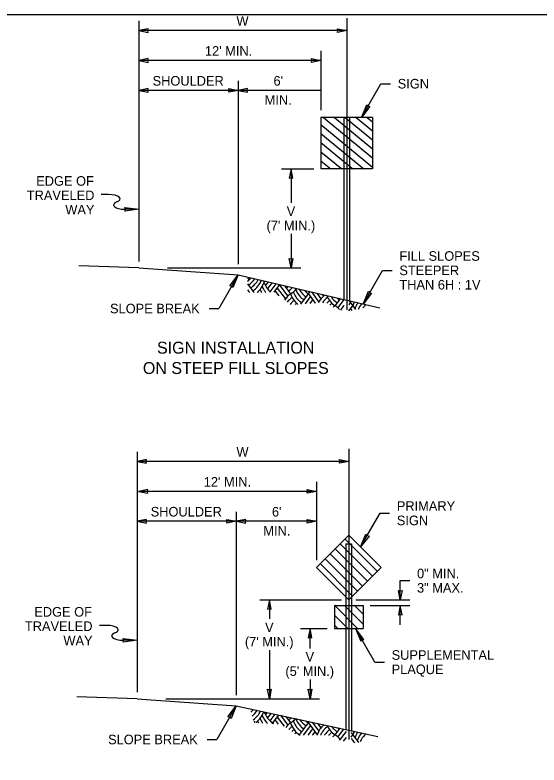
# Model space of a CAD drawing. Extents: x 99862 to 104211, y 98939 to 102076.
# Drawn here: x 100694 to 101570, y 100822 to 102076 of the extents above; entities that cross this region are included whole.
import ezdxf

# ---------------------------------------------------------------- set-up
doc = ezdxf.new("R2010")
doc.units = 0
for name, color, linetype in [('Level 1', 7, 'Continuous'), ('Level 14', 7, 'Continuous'), ('Level 15', 7, 'Continuous'), ('Level 2', 7, 'Continuous'), ('Level 20', 7, 'Continuous'), ('Level 6', 7, 'Continuous')]:
    doc.layers.add(name, color=color, linetype=linetype)

msp = doc.modelspace()

# ---------------------------------------------------------------- linework, layer by layer
at = {"layer": 'Level 1'}
msp.add_lwpolyline([(99862, 99999.5), (103151, 99999.5), (103151, 102075.5), (99862, 102075.5)], close=True, dxfattribs=at)
msp.add_lwpolyline([(99862, 99999.5), (103151, 99999.5), (103151, 102075.5), (99862, 102075.5)], close=True, dxfattribs=at)
at = {"layer": 'Level 14'}
for p, q in [((100850.7, 101775.4), (100838.4, 101775.4)), ((100897.2, 101750.8), (100878, 101750.8)), ((100847.5, 101055.4), (100835.2, 101055.4)), ((100894, 101030.8), (100874.8, 101030.8))]:
    msp.add_line(p, q, dxfattribs=at)
for points in [[(100901.2, 101750.8), (100877.9, 101747.8), (100879, 101750.8), (100877.9, 101753.9)], [(100898.1, 101030.8), (100874.7, 101027.7), (100875.8, 101030.8), (100874.7, 101033.8)]]:
    msp.add_lwpolyline(points, close=True, dxfattribs=at)
for centre, start_param, end_param in [((100850.8, 101768.2), 5.497747, 7.861127), ((100878, 101758), 2.356226, 4.712389), ((100847.7, 101048.2), 5.497747, 7.861127), ((100874.8, 101038), 2.356226, 4.712389)]:
    msp.add_ellipse(centre, major_axis=(19.2, 0), ratio=0.375, start_param=start_param, end_param=end_param, dxfattribs=at)
at = {"layer": 'Level 15'}
for p, q in [((100901.2, 102065.5), (100901.2, 101663.8)), ((101248.9, 102049.5), (100901.2, 102049.5)), ((101205.5, 102015.5), (101205.5, 101916.4)), ((101205.5, 101999.5), (100901.2, 101999.5)), ((101067.1, 101965.5), (101067.1, 101659.1)), ((101273.3, 101904.4), (101305.8, 101960.7)), ((101305.8, 101960.7), (101321.8, 101960.7)), ((101067.1, 101949.5), (100901.2, 101949.5)), ((101205.5, 101949.5), (101067.1, 101949.5)), ((101139.6, 101818.3), (101193.5, 101818.3)), ((101155.6, 101818.3), (101155.6, 101761.7)), ((101155.6, 101709.7), (101155.6, 101653.1)), ((100949.2, 101653.1), (101171.6, 101653.1)), ((101067.1, 101641.3), (101034.6, 101585)), ((101276.1, 101592.5), (101308.6, 101648.8)), ((101308.6, 101648.8), (101324.6, 101648.8)), ((101018.6, 101585), (101034.6, 101585)), ((100898.1, 101345.5), (100898.1, 100943.8)), ((101252, 101329.5), (100898.1, 101329.5)), ((101197.9, 101295.5), (101197.9, 101164.4)), ((101197.9, 101279.5), (100900.5, 101279.5)), ((101064, 101245.5), (101064, 100939.1)), ((101271.8, 101186.7), (101304.3, 101243)), ((101304.3, 101243), (101320.3, 101243)), ((101064, 101229.5), (100898.1, 101229.5)), ((101197.9, 101229.5), (101064, 101229.5)), ((101338.1, 101130.3), (101354.1, 101130.3)), ((101338.1, 101098.3), (101338.1, 101130.3)), ((101103.4, 101098.3), (101240, 101098.3)), ((101119.4, 101098.3), (101119.4, 101066.3)), ((101264, 101098.3), (101354.1, 101098.3)), ((101287.9, 101088.7), (101354.1, 101088.7)), ((101338.1, 101056.7), (101338.1, 101088.7)), ((101171.2, 101050.4), (101216.1, 101050.4)), ((101187.2, 101017.1), (101187.2, 101050.4)), ((101295.6, 100994.1), (101263.1, 101050.4)), ((101119.4, 101014.3), (101119.4, 100933.1)), ((101295.6, 100994.1), (101311.6, 100994.1)), ((101187.2, 100965.1), (101187.2, 100933.1)), ((100946.1, 100933.1), (101203.2, 100933.1)), ((101064, 100921.2), (101031.5, 100864.9)), ((101015.5, 100864.9), (101031.5, 100864.9))]:
    msp.add_line(p, q, dxfattribs=at)
for points in [[(100901.2, 102049.5), (100917, 102046.4), (100916.2, 102049.5), (100917, 102052.6)], [(101248.9, 102049.5), (101233.1, 102046.4), (101233.9, 102049.5), (101233.1, 102052.6)], [(100901.2, 101999.5), (100917, 101996.4), (100916.2, 101999.5), (100917, 102002.6)], [(101205.5, 101999.5), (101189.7, 101996.4), (101190.5, 101999.5), (101189.7, 102002.6)], [(100901.2, 101949.5), (100917, 101946.4), (100916.2, 101949.5), (100917, 101952.6)], [(101067.1, 101949.5), (101051.4, 101946.4), (101052.2, 101949.5), (101051.4, 101952.6)], [(101067.1, 101949.5), (101082.9, 101946.4), (101082.1, 101949.5), (101082.9, 101952.6)], [(101273.3, 101904.4), (101282.2, 101925.6), (101284.2, 101923.2), (101287.3, 101922.7)], [(101155.6, 101818.3), (101152.5, 101802.6), (101155.6, 101803.3), (101158.7, 101802.6)], [(101155.6, 101653.1), (101152.5, 101668.8), (101155.6, 101668.1), (101158.7, 101668.8)], [(101067.1, 101641.3), (101058.3, 101620), (101056.3, 101622.4), (101053.1, 101623)], [(101276.1, 101592.5), (101284.9, 101613.8), (101287, 101611.3), (101290.1, 101610.8)], [(100898.1, 101329.5), (100913.8, 101326.4), (100913.1, 101329.5), (100913.8, 101332.5)], [(101252, 101329.5), (101236.3, 101326.4), (101237, 101329.5), (101236.3, 101332.5)], [(100900.5, 101279.5), (100916.2, 101276.4), (100915.5, 101279.5), (100916.2, 101282.5)], [(101197.9, 101279.5), (101182.2, 101276.4), (101182.9, 101279.5), (101182.2, 101282.5)], [(100898.1, 101229.5), (100913.8, 101226.4), (100913.1, 101229.5), (100913.8, 101232.5)], [(101064, 101229.5), (101048.3, 101226.4), (101049, 101229.5), (101048.3, 101232.5)], [(101064, 101229.5), (101079.7, 101226.4), (101079, 101229.5), (101079.7, 101232.5)], [(101197.9, 101229.5), (101182.2, 101226.4), (101182.9, 101229.5), (101182.2, 101232.5)], [(101271.8, 101186.7), (101280.6, 101207.9), (101282.7, 101205.5), (101285.8, 101204.9)], [(101338.1, 101098.3), (101335, 101114), (101338.1, 101113.2), (101341.2, 101114)], [(101119.4, 101098.3), (101116.4, 101082.5), (101119.4, 101083.3), (101122.5, 101082.5)], [(101338.1, 101088.7), (101335, 101073), (101338.1, 101073.7), (101341.2, 101073)], [(101187.2, 101050.4), (101184.1, 101034.7), (101187.2, 101035.4), (101190.3, 101034.7)], [(101263.1, 101050.4), (101271.9, 101029.2), (101273.9, 101031.6), (101277.1, 101032.2)], [(101119.4, 100933.1), (101116.4, 100948.8), (101119.4, 100948.1), (101122.5, 100948.8)], [(101187.2, 100933.1), (101184.1, 100948.8), (101187.2, 100948.1), (101190.3, 100948.8)], [(101064, 100921.2), (101055.2, 100900), (101053.1, 100902.4), (101050, 100902.9)]]:
    msp.add_lwpolyline(points, close=True, dxfattribs=at)
at = {"layer": 'Level 2'}
for p, q in [((101248.5, 102070.3), (101248.5, 101582.9)), ((101205.5, 101904.4), (101205.5, 101818.3)), ((101291.5, 101904.4), (101205.5, 101904.4)), ((101209.5, 101904.4), (101291.5, 101836.6)), ((101227.9, 101904.4), (101291.5, 101851.7)), ((101243.7, 101904.4), (101243.7, 101818.3)), ((101246.2, 101904.4), (101291.5, 101866.9)), ((101253.3, 101904.4), (101253.3, 101818.3)), ((101264.6, 101904.4), (101291.5, 101882.1)), ((101282.9, 101904.4), (101291.5, 101897.2)), ((101291.5, 101904.4), (101291.5, 101818.3)), ((101205.5, 101892.6), (101291.5, 101821.4)), ((101205.5, 101877.4), (101276.9, 101818.3)), ((101205.5, 101862.2), (101258.6, 101818.3)), ((101205.5, 101847.1), (101240.3, 101818.3)), ((101205.5, 101831.9), (101221.9, 101818.3)), ((101291.5, 101818.3), (101205.5, 101818.3)), ((101243.7, 101818.3), (101243.7, 101600.1)), ((101253.3, 101818.3), (101253.3, 101597.8)), ((100901.2, 101653.1), (100800.8, 101656.2)), ((100901.2, 101653.1), (101067.1, 101641.3)), ((101067.1, 101641.3), (101303.9, 101586)), ((101252, 101350.3), (101252, 100864.6)), ((101252, 101206.5), (101197.9, 101152.4)), ((101245.6, 101200.1), (101299.7, 101146)), ((101306.1, 101152.4), (101252, 101206.5)), ((101237.4, 101191.8), (101291.5, 101137.7)), ((101247.2, 101191.7), (101256.8, 101191.7)), ((101247.2, 101191.7), (101247.2, 101105)), ((101256.8, 101191.7), (101256.8, 101103.9)), ((101220.8, 101175.3), (101274.9, 101121.2)), ((101229.1, 101183.5), (101283.2, 101129.4)), ((101212.6, 101167), (101266.7, 101112.9)), ((101197.9, 101152.4), (101252, 101098.3)), ((101204.3, 101158.7), (101258.4, 101104.6)), ((101252, 101098.3), (101306.1, 101152.4)), ((101247.2, 101103.6), (101247.2, 101088.7)), ((101256.8, 101103.3), (101256.8, 101089.3)), ((101228.1, 101089.1), (101266.8, 101050.4)), ((101228.1, 101088.7), (101275.9, 101088.7)), ((101228.1, 101088.7), (101228.1, 101050.4)), ((101245, 101088.7), (101275.9, 101057.8)), ((101247.2, 101088.7), (101247.2, 101050.4)), ((101256.8, 101089.3), (101256.8, 101050.4)), ((101261, 101089.3), (101275.9, 101074.3)), ((101275.9, 101088.7), (101275.9, 101050.4)), ((101228.1, 101072.6), (101250.2, 101050.4)), ((101228.1, 101056), (101233.7, 101050.4)), ((101228.1, 101050.4), (101275.9, 101050.4)), ((101247.2, 101050.4), (101247.2, 100881.6)), ((101256.8, 101050.4), (101256.8, 100879.5)), ((100898.1, 100933.1), (100797.6, 100936.2)), ((100898.1, 100933.1), (101064, 100921.2)), ((101064, 100921.2), (101300.3, 100870.1))]:
    msp.add_line(p, q, dxfattribs=at)
msp.add_lwpolyline([(101067.1, 101641.3), (101065.3, 101639.4), (101065.8, 101639.2), (101066.1, 101638.9)], close=True, dxfattribs=at)
at = {"layer": 'Level 6'}
for p, q in [((101082.6, 101636.4), (101085.3, 101632.9)), ((101082.7, 101626.4), (101093.6, 101611.8)), ((101110.3, 101629.2), (101111.6, 101630.9)), ((101113, 101622.9), (101117.9, 101629.4)), ((101116.4, 101617.6), (101124.2, 101627.9)), ((101120.5, 101613.1), (101130.5, 101626.5)), ((101127.2, 101612.1), (101136.8, 101625)), ((101082.8, 101616.4), (101086.3, 101611.7)), ((101128.9, 101614.3), (101135, 101606.1)), ((101132.6, 101619.3), (101146.1, 101601.2)), ((101136.3, 101624.2), (101150.2, 101605.7)), ((101144.5, 101623.2), (101154.8, 101609.4)), ((101179.9, 101613.1), (101181.1, 101614.7)), ((101184.5, 101609.4), (101187.4, 101613.2)), ((101189.5, 101612.7), (101202.1, 101595.9)), ((101171.7, 101592.3), (101184.5, 101609.4)), ((101179.5, 101592.8), (101188.3, 101604.4)), ((101184.5, 101609.4), (101196.1, 101593.9)), ((101187.4, 101593.4), (101192, 101599.5)), ((101198.5, 101610.6), (101205.5, 101601.2)), ((101207.5, 101608.5), (101209.6, 101605.7)), ((101229.1, 101589.6), (101237.9, 101601.4)), ((101236.5, 101589.6), (101244.3, 101599.9)), ((101195.2, 101593.9), (101195.7, 101594.5)), ((101233.7, 101585.9), (101236.5, 101589.6)), ((101238.6, 101582.5), (101243.9, 101589.6)), ((101243.9, 101589.6), (101244.5, 101590.3)), ((101252.3, 101581), (101258.8, 101589.6)), ((101252.5, 101598), (101258.8, 101589.6)), ((101252.5, 101591.1), (101255.1, 101594.5)), ((101258.8, 101589.6), (101263.5, 101583.4)), ((101255.1, 101584.6), (101257.1, 101582)), ((101113, 100905.9), (101116, 100910)), ((101116.4, 100900.6), (101122.4, 100908.6)), ((101120.5, 100896.2), (101128.8, 100907.2)), ((101125.1, 100892.5), (101135.2, 100905.8)), ((101132.6, 100902.4), (101144.1, 100887)), ((101137.8, 100905.3), (101150.2, 100888.8)), ((101146.7, 100903.3), (101154.8, 100892.5)), ((101093.1, 100895.6), (101094.9, 100893.2)), ((101124.2, 100891.2), (101125.1, 100892.5)), ((101125.1, 100892.5), (101126.2, 100891.1)), ((101128.9, 100897.4), (101134, 100890.6)), ((101169.7, 100872.7), (101184.5, 100892.5)), ((101177.1, 100872.7), (101188.3, 100887.5)), ((101184.5, 100892.5), (101186.3, 100894.8)), ((101184.5, 100892.5), (101199.4, 100872.7)), ((101191, 100893.8), (101202.1, 100879)), ((101199.9, 100891.8), (101205.5, 100884.3)), ((101208.7, 100889.9), (101209.6, 100888.8)), ((101176.6, 100872), (101177.1, 100872.7)), ((101184, 100872), (101184.5, 100872.7)), ((101184.5, 100872.7), (101192, 100882.6)), ((101191.5, 100872), (101192, 100872.7)), ((101192, 100872.7), (101195.7, 100877.6)), ((101198.9, 100872), (101199.4, 100872.7)), ((101199.4, 100872.7), (101199.9, 100872)), ((101229.1, 100872.7), (101237.4, 100883.7)), ((101233.7, 100869), (101236.5, 100872.7)), ((101236.5, 100872.7), (101243.8, 100882.4)), ((101237.8, 100864.5), (101243.9, 100872.7)), ((101243.9, 100872.7), (101248, 100878.1)), ((101256, 100876.4), (101258.8, 100872.7)), ((101256, 100869), (101258.8, 100872.7)), ((101258.8, 100872.7), (101268.5, 100859.7)), ((101243.3, 100861.9), (101248, 100868.2)), ((101256, 100866.5), (101261.4, 100859.3))]:
    msp.add_line(p, q, dxfattribs=at)
for centre, start, end in [((101059.6, 101660.4), 307.7663, 320.1115), ((101063.4, 101655.4), 303.9036, 326.7235), ((101067.1, 101650.5), 303.9036, 333.0655), ((101070.8, 101645.5), 303.9036, 339.2388), ((101074.5, 101640.6), 310.1733, 342.3566), ((101074.5, 101617.8), 17.6434, 21.1585), ((101146.1, 101640.6), 197.6435, 229.0424), ((101135, 101625.7), 200.2432, 201.6183), ((101138.7, 101630.7), 201.4344, 209.8527), ((101142.4, 101635.6), 200.8778, 211.332), ((101142.4, 101635.6), 211.3319, 218.8105), ((101126.5, 101650.5), 303.9036, 310.1516), ((101130.2, 101645.5), 303.9036, 317.3928), ((101133.9, 101640.6), 303.9036, 324.1475), ((101194.4, 101625.7), 200.2432, 228.9599), ((101198.1, 101630.7), 201.4344, 220.9416), ((101201.8, 101635.6), 208.823, 211.332), ((101201.8, 101635.6), 211.3319, 236.0964), ((101205.5, 101640.6), 221.8819, 236.0964), ((101175.8, 101578.2), 123.9036, 146.5738), ((101179.5, 101573.3), 126.3063, 144.014), ((101190.7, 101620.8), 197.6434, 230.0572), ((101198.1, 101630.7), 220.9415, 236.0964), ((101235.2, 101578.2), 128.7283, 154.684), ((101238.9, 101573.3), 126.3063, 145.1518), ((101250.1, 101620.8), 202.0131, 236.0964), ((101253.8, 101625.7), 213.4529, 228.9599), ((101257.5, 101630.7), 228.1677, 236.0964), ((101183.2, 101568.3), 127.1006, 141.4571), ((101186.9, 101563.4), 126.331, 131.0608), ((101194.4, 101625.7), 228.9599, 236.0964), ((101242.6, 101568.3), 127.1006, 136.9498), ((101246.3, 101563.4), 126.331, 133.3175), ((101250.1, 101558.4), 123.9036, 129.6201), ((101253.8, 101625.7), 228.9599, 236.0964), ((101208.1, 101558.4), 41.2677, 56.0963), ((101294.6, 101578.2), 151.8986, 162.3566), ((101298.3, 101573.3), 154.2265, 162.3566), ((101298.3, 101573.3), 145.5149, 154.2266), ((101302, 101568.3), 145.491, 155.0119), ((101302, 101568.3), 138.8385, 145.4911), ((101305.7, 101563.4), 135.7127, 143.8759), ((101305.7, 101563.4), 131.7169, 135.7128), ((101063.4, 100938.5), 311.6126, 321.2972), ((101067.1, 100933.6), 308.3274, 328.0221), ((101070.8, 100928.6), 305.1105, 334.4729), ((101074.5, 100923.7), 305.6221, 340.7553), ((101146.1, 100923.7), 199.4957, 236.0964), ((101138.7, 100913.8), 201.4344, 214.7633), ((101142.4, 100918.7), 200.8778, 211.332), ((101142.4, 100918.7), 211.3319, 225.8186), ((101126.5, 100933.6), 303.9036, 305.5448), ((101130.2, 100928.6), 303.9036, 313.4276), ((101133.9, 100923.7), 303.9036, 320.6254), ((101198.1, 100913.8), 201.8714, 220.9416), ((101201.8, 100918.7), 213.0226, 236.0964), ((101135, 100908.8), 200.2432, 205.2177), ((101175.8, 100861.3), 123.9036, 140.5875), ((101179.5, 100856.3), 126.3063, 137.6347), ((101190.7, 100903.9), 197.6434, 236.0964), ((101194.4, 100908.8), 200.2432, 228.9599), ((101198.1, 100913.8), 220.9415, 236.0964), ((101205.5, 100923.7), 227.058, 236.0964), ((101235.2, 100861.3), 131.2195, 162.3566), ((101238.9, 100856.3), 126.3063, 154.2266), ((101250.1, 100903.9), 204.3154, 236.0964), ((101253.8, 100908.8), 215.9306, 228.9599), ((101183.2, 100851.4), 127.1006, 134.6621), ((101186.9, 100846.4), 126.331, 131.661), ((101190.7, 100841.5), 123.9036, 125.7348), ((101194.4, 100908.8), 228.9599, 236.0964), ((101148.7, 100841.5), 54.2652, 56.0963), ((101238.9, 100856.3), 154.2265, 155.3821), ((101242.6, 100851.4), 145.491, 146.7505), ((101242.6, 100851.4), 127.1006, 145.4911), ((101246.3, 100846.4), 135.7127, 137.9182), ((101246.3, 100846.4), 126.331, 135.7128), ((101250.1, 100841.5), 123.9036, 132.5201), ((101253.8, 100908.8), 228.9599, 236.0964), ((101208.1, 100841.5), 36.418, 56.0963), ((101257.5, 100913.8), 231.2177, 236.0964), ((101294.6, 100861.3), 152.6176, 162.3566), ((101298.3, 100856.3), 154.2265, 162.3566), ((101298.3, 100856.3), 146.0993, 154.2266), ((101302, 100851.4), 145.491, 162.3566), ((101302, 100851.4), 139.2697, 145.4911), ((101305.7, 100846.4), 135.7127, 156.4253), ((101305.7, 100846.4), 131.9625, 135.7128)]:
    msp.add_arc(centre, 37.6, start, end, dxfattribs=at)

# ---------------------------------------------------------------- texts
at = {"layer": 'Level 2'}
for s, p in [('SIGN INSTALLATION', (100931.5, 101509.6)), ('ON STEEP FILL SLOPES', (100907.9, 101475.6))]:
    msp.add_text(s, height=20, dxfattribs=at).set_placement(p)
at = {"layer": 'Level 20'}
for s, p in [('W', (101064.3, 102057.5)), ("12' MIN.", (101011.6, 102007.5)), ('SHOULDER', (100924.2, 101957.5)), ("6'", (101126.2, 101957.5)), ('SIGN', (101333.8, 101952.7)), ('MIN.', (101111.5, 101925.5)), ('EDGE OF', (100729.7, 101790.2)), ('TRAVELED', (100713.9, 101766.2)), ('WAY', (100778.3, 101742.2)), ('V', (101148.3, 101739.7)), ("(7' MIN.)", (101114.6, 101715.7)), ('FILL SLOPES', (101336.6, 101664.8)), ('STEEPER', (101336.6, 101640.8)), ('THAN 6H : 1V', (101336.6, 101616.8)), ('SLOPE BREAK', (100853, 101577)), ('W', (101064.3, 101337.5)), ("12' MIN.", (101009.7, 101287.5)), ('PRIMARY', (101332.3, 101247)), ('SHOULDER', (100921, 101237.5)), ("6'", (101123.6, 101237.5)), ('SIGN', (101332.3, 101223)), ('MIN.', (101109.2, 101205.5)), ('0" MIN.', (101366.1, 101134.3)), ('3" MAX.', (101366.1, 101110.3)), ('EDGE OF', (100726.5, 101070.2)), ('TRAVELED', (100710.8, 101046.2)), ('V', (101112.1, 101044.3)), ('WAY', (100775.1, 101022.2)), ("(7' MIN.)", (101078.4, 101020.3)), ('V', (101179.8, 100995.1)), ('SUPPLEMENTAL', (101323.6, 100998.1)), ("(5' MIN.)", (101146.1, 100971.1)), ('PLAQUE', (101323.6, 100974.1)), ('SLOPE BREAK', (100849.8, 100856.9))]:
    msp.add_text(s, height=16, dxfattribs=at).set_placement(p)

doc.saveas('drawing.dxf')
